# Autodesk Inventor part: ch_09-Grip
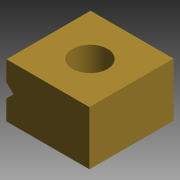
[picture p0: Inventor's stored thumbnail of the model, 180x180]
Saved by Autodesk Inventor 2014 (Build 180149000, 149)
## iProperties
Shininess: 0.0
Length Units: 11272
Angle Units: 11279
Time Units: 11290
Mass Units: 11283
Length Display Precision: 2
Angle Display Precision: 1
Compacted: True
Created: 1999-05
Part Number: ch_09-Grip
Document SubType Name: Modeling
Designer: Administrator
Density: 7.86 g/cm^3
Material: Steel, Mild
Mass: 29.2088 g
Surface Area: 18.6387 cm^2
Volume: 3.71614 cm^3
Appearance: Metal - Gold
Density: 0.0
Volumn: 0.0
Area: 0.0
PropertySet Name: Model Information
Control State: 0
Master: False
Checked Out: False
Author: Administrator
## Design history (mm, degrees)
node "y-z Plane"
  node "x-z Plane"
  node "x-y Plane"
node "Extrusion1" dims "d2" = 19.05, "d3" = 0
  sketch "Sketch1"
    geometry: L1 (-9.398, -6.096)-(9.398, -6.096); L2 (9.398, -6.096)-(9.398, 6.096); L3 (9.398, 6.096)-(-9.398, 6.096); L4 (-9.398, 6.096)-(-9.398, -6.096); 1 further point
    constraints: 8 end point, 2 parallel, 1 horizontal, 1 perpendicular
    dimensions: "d0" = 18.796 distance of L1.start L1.end; "d1" = 12.192 distance of L1.end L2.end; "d17" = 9.398 distance from line of point (0, 0) L2 (= 0.5 x d0); "d18" = 6.096 distance from line of point (0, 0) L1 (= 0.5 x d1)
node "Extrusion2" dims "d7" = 19.05, "d8" = 0
  sketch "Sketch2"
    geometry: L1 (-9.398, 6.096)-(-9.398, -6.096) reference; L2 (-9.398, -1.588)-(-7.81, 0); L3 (-7.81, 0)-(-9.398, 1.588); 1 further point
    constraints: 4 end point, 2 point on line, 1 horizontal alignment, 1 perpendicular
    dimensions: "d4" = 1.5875 horizontal distance of L2.end L2.start; "d6" = 90 deg angle of L3 L2
node "Hole1" dims "d11" = 7.9248, "d12" = 9.525, "d13" = 6.35, "d14" = 60 deg, "d15" = 19.05, "d16" = 118 deg
  sketch "Sketch3"
    geometry: 2 further points
    constraints: 1 coincident
body "Solid1"
